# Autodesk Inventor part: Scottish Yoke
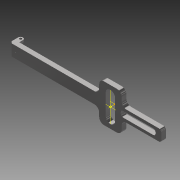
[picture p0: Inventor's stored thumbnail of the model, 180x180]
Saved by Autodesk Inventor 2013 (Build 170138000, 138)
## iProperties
Created: 2008-06
Part Number: Scottish Yoke
Document SubType Name: Modeling
Designer: tangg
Density: 7.84 g/cm^3
Mass: 21.4252 g
Surface Area: 112.705 cm^2
Volume: 21.4252 cm^3
Stock Number: Scottish Yoke
Material: Steel, High Strength Low Alloy
Author: tangg
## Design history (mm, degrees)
sketch "Sketch1"
  geometry: L1 (195.262, 4.445)-(195.262, -4.445); L2 (-7.938, -7.62)-(-7.938, 7.62); L3 (111.919, 25.4)-(142.081, 25.4); L4 (142.081, -25.4)-(111.919, -25.4); L5 (127, 42.862)-(127, -39.687); L6 (127, 19.844)-(127, 19.844); L7 (133.35, 13.494)-(133.35, -13.494); L8 (127, -19.844)-(127, -19.844); L9 (120.65, -13.494)-(120.65, 13.494); L10 (-7.938, 7.62)-(111.919, 7.62); L11 (142.081, 7.62)-(192.088, 7.62); L12 (192.088, -7.62)-(142.081, -7.62); L13 (111.919, -7.62)-(-7.938, -7.62); L14 (111.919, -25.4)-(111.919, -7.62); L15 (111.919, 7.62)-(111.919, 25.4); L16 (142.081, 25.4)-(142.081, 7.62); L17 (142.081, -7.62)-(142.081, -25.4); C1 r 0.408 at (0, 0); A1 r 3.175 centre (192.088, 4.445) between (195.262, 4.445) and (192.088, 7.62); A2 r 3.175 centre (192.088, -4.445) between (192.088, -7.62) and (195.262, -4.445); A3 r 6.35 centre (127, 13.494) between (127, 19.844) and (120.65, 13.494); A4 r 6.35 centre (127, 13.494) between (133.35, 13.494) and (127, 19.844); A5 r 6.35 centre (127, -13.494) between (127, -19.844) and (133.35, -13.494); A6 r 6.35 centre (127, -13.494) between (120.65, -13.494) and (127, -19.844); 6 further points
  constraints: 34 end point, 14 tangent, 12 point on circle, 7 centre point, 4 equal radius, 4 midpoint, 3 horizontal alignment, 2 point on line, 1 coincident
  dimensions: "d0" = 15.24 distance of L2.start L2.end; "d1" = 203.2 distance between parallel lines of L1 L2; "d2" = 3.175 radius of A1; "d3" = 127 distance from line of L5 point (0, 0); "d4" = 6.35 radius of A3; "d43" = 25.4 distance from line of point (120.65, 0) L3; "d44" = 25.4 distance of point (111.919, 0) L4.end
extrude "Extrusion1" new body sketch "Sketch1" distance "d5" = 6.35; taper "d6" = 0 deg
workplane "Work Plane3"
workpoint "Work Point2"
  workaxis "Work Axis1"
workaxis "Work Axis2"
workaxis "Work Axis3"
fillet "Fillet1" dims "d20" = 6.35
sketch "Sketch10"
  geometry: L1 (144.049, 3.81)-(184.417, 3.81); L2 (187.592, 0.635)-(187.592, -0.635); L3 (184.417, -3.81)-(144.049, -3.81); L4 (140.874, -0.635)-(140.874, 0.635); L5 (135.731, -25.4)-(118.269, -25.4) reference; L6 (192.088, -7.62)-(148.431, -7.62) reference; L7 (195.262, 4.445)-(195.262, -4.445) reference; L8 (148.431, 7.62)-(192.088, 7.62) reference; L9 (118.269, 25.4)-(135.731, 25.4) reference; L10 (-7.938, 7.62)-(105.569, 7.62) reference; L11 (-7.938, -7.62)-(-7.938, 7.62) reference; L12 (105.569, -7.62)-(-7.938, -7.62) reference; L13 (133.35, 13.494)-(133.35, -13.494) reference; L14 (120.65, -13.494)-(120.65, 13.494) reference; L15 (-7.938, 7.62)-(82.337, 7.62); L16 (82.337, 7.62)-(89.968, 7.62); L17 (195.262, 4.445)-(195.262, -4.445) reference; L18 (-7.938, 0)-(195.263, 0); L19 (-7.938, -7.62)-(82.337, -7.62); L20 (82.337, -7.62)-(89.968, -7.62); L21 (142.081, -13.97)-(142.081, -19.05) reference; L22 (142.081, 19.05)-(142.081, 13.97) reference; L23 (111.919, 13.97)-(111.919, 19.05) reference; L24 (111.919, -19.05)-(111.919, -13.97) reference; C1 r 0.408 at (0, 0) reference; A1 r 6.35 centre (118.269, -19.05) between (111.919, -19.05) and (118.269, -25.4) reference; A2 r 6.35 centre (135.731, -19.05) between (135.731, -25.4) and (142.081, -19.05) reference; A3 r 6.35 centre (148.431, -13.97) between (148.431, -7.62) and (142.081, -13.97) reference; A4 r 3.175 centre (192.088, -4.445) between (192.088, -7.62) and (195.262, -4.445) reference; A5 r 3.175 centre (192.088, 4.445) between (195.262, 4.445) and (192.088, 7.62) reference; A6 r 6.35 centre (148.431, 13.97) between (142.081, 13.97) and (148.431, 7.62) reference; A7 r 6.35 centre (135.731, 19.05) between (142.081, 19.05) and (135.731, 25.4) reference; A8 r 6.35 centre (118.269, 19.05) between (118.269, 25.4) and (111.919, 19.05) reference; A9 r 6.35 centre (105.569, 13.97) between (105.569, 7.62) and (111.919, 13.97) reference; A10 r 6.35 centre (105.569, -13.97) between (111.919, -13.97) and (105.569, -7.62) reference; A11 r 6.35 centre (127, 13.494) between (133.35, 13.494) and (120.65, 13.494) reference; A12 r 6.35 centre (127, -13.494) between (120.65, -13.494) and (133.35, -13.494) reference; A13 r 3.175 centre (144.049, 0.635) between (144.049, 3.81) and (140.874, 0.635); A14 r 3.175 centre (144.049, -0.635) between (140.874, -0.635) and (144.049, -3.81); A15 r 3.175 centre (184.417, 0.635) between (187.592, 0.635) and (184.417, 3.81); A16 r 3.175 centre (184.417, -0.635) between (184.417, -3.81) and (187.592, -0.635); 3 further points
  constraints: 18 end point, 8 point on circle, 8 tangent, 4 centre point, 4 midpoint, 4 point on line, 2 equal radius, 2 horizontal alignment, 1 horizontal, 1 parallel
  dimensions: "d22" = 3.175 radius of A13; "d23" = 7.62 distance between parallel lines of L3 L1; "d24" = 3.175 radius of A15; "d25" = 7.62 distance from line of point (0, 0) L15; "d26" = 7.62 distance of L19.start L18.start
extrude "Extrusion7" cut sketch "Sketch10" stored distance "d27" = 19.05; taper "d28" = 0 deg
sketch "Sketch7"
  geometry: L1 (7.938, 0)-(7.938, -5); L2 (7.938, 0)-(-19.05, 0); L3 (-111.919, 0)-(7.938, 0) reference; L4 (7.938, 0)-(1.588, 0); L5 (1.588, 0)-(1.588, -5); L6 (7.938, -5)-(7.938, 0); L7 (1.588, -5)-(3.175, -5); L8 (6.35, -5)-(7.938, -5); L9 (7.938, 0)-(-111.919, 0) reference; A1 r 3.175 centre (4.763, -5) between (1.588, -5) and (7.938, -5); A2 r 1.587 centre (4.763, -5) between (3.175, -5) and (6.35, -5); 2 further points
  constraints: 14 end point, 4 point on circle, 2 centre point, 2 coincident, 2 collinear, 2 parallel, 1 point on line, 1 vertical
  dimensions: "d35" = 6.35 distance of L3.end L4.end; "d40" = 5 distance of L1.start L1.end; "d41" = 3.175 radius of A1; "d42" = 3.175 diameter of A2
extrude "Extrusion9" join sketch "Sketch7" stored distance "d36" = 15.24; taper "d37" = 0 deg
sketch "Sketch12"
  geometry: L1 (1.588, 0)-(7.938, 0); L2 (7.938, 6.35)-(7.938, -5) reference; L3 (1.588, -5)-(1.588, 0) reference; A1 r 3.175 centre (4.763, -5) between (1.588, -5) and (7.938, -5) reference; A2 r 3.175 centre (4.763, -5) between (1.588, -5) and (7.938, -5) reference; 1 further point
  constraints: 2 end point, 1 point on line
extrude "Extrusion11" cut sketch "Sketch12" stored distance "d45" = 7.62; taper "d46" = 0 deg
chamfer "Chamfer1" distance "d47" = 2.54; stored, may be unused: second distance "d48" = 3.175, angle "d49" = 45 deg
workpoint "Work Point4"
workaxis "Work Axis5"
body "Solid1"
node "Projected Loop6"
node "Projected Loop7"
other parameters: "d30" = 6.35, "d34" = 6.35
